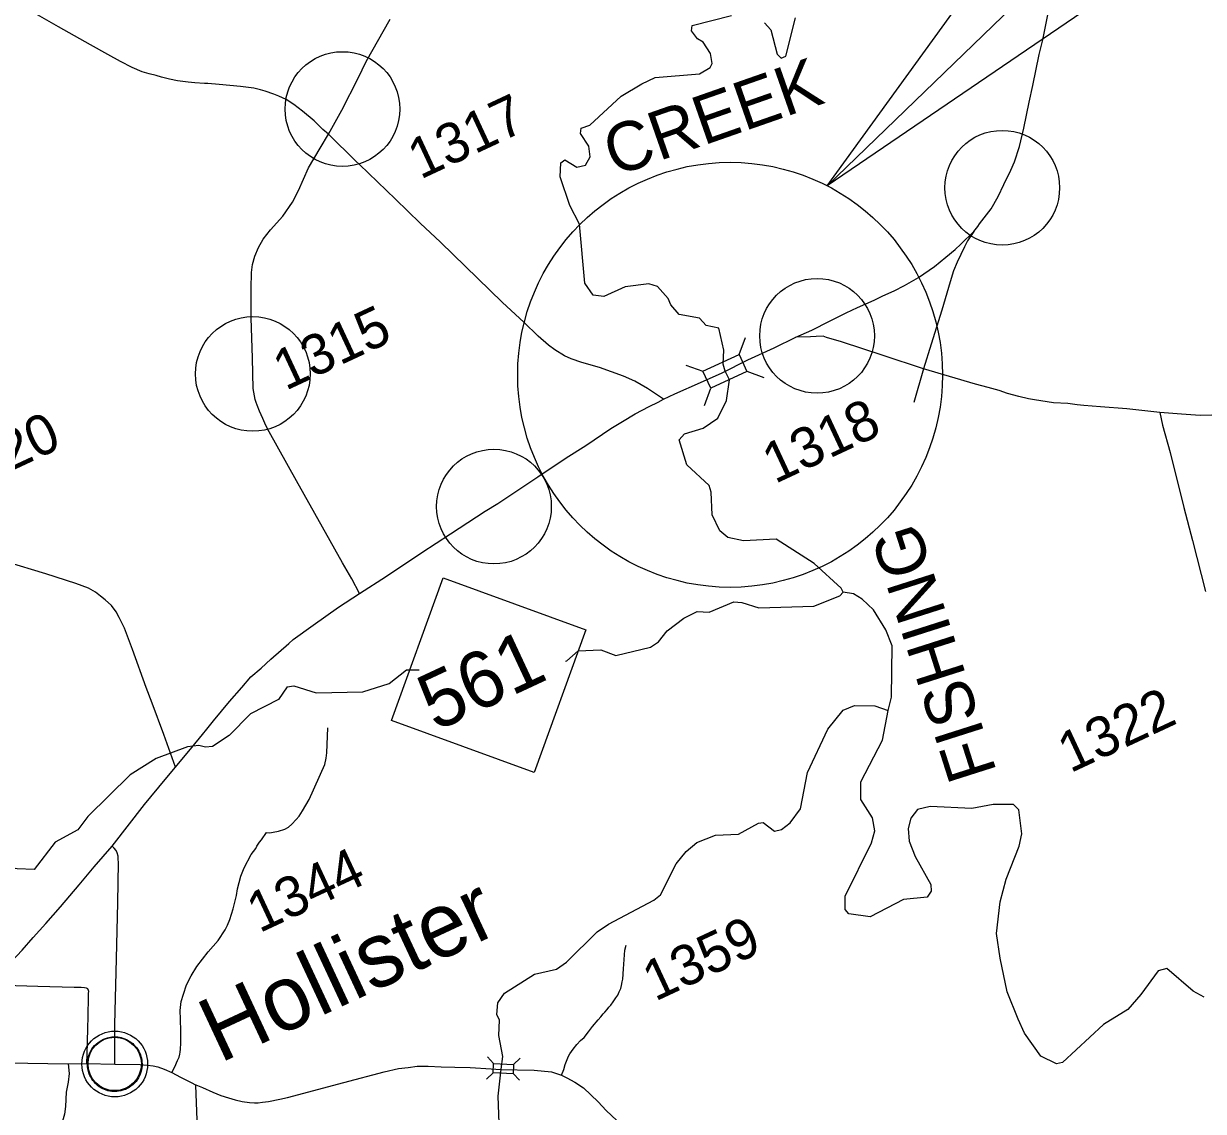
# Model space of a CAD drawing. Extents: x 2318983 to 2324558, y 920396 to 924651.
# Drawn here: x 2320442.5 to 2320802.7, y 922779.6 to 923111.6 of the extents above; entities that cross this region are included whole.
import ezdxf

# ---------------------------------------------------------------- set-up
doc = ezdxf.new("R2010")
doc.units = 0
for name, color, linetype in [('Default', 7, 'Continuous'), ('Exist Civil Demographics City Label', 7, 'Continuous'), ('Exist Civil Demographics Community CELL', 7, 'Continuous'), ('Exist Hydrographic Creek Single Shore', 7, 'Continuous'), ('Exist Road Primary NC Attributed', 7, 'Continuous'), ('Exist Road Primary NC Shield CELL', 7, 'Continuous'), ('Exist Road Primary NC Shield Number Label', 7, 'Continuous'), ('Exist Road Primary NC Structure Standard Bridge CELL', 7, 'Continuous'), ('Exist Road Secondary Structure Standard Bridge CELL', 7, 'Continuous'), ('Exist Road Secondary Type 41 Attributed', 7, 'Continuous'), ('Exist Road Secondary Type 51 Attributed', 7, 'Continuous'), ('Exist Road Secondary Type 51 Number Label', 7, 'Continuous'), ('Pattern 3', 7, 'Continuous'), ('Prop Terminator CELL', 7, 'Continuous')]:
    doc.layers.add(name, color=color, linetype=linetype)

msp = doc.modelspace()

# ---------------------------------------------------------------- linework, layer by layer
at = {"layer": 'Exist Civil Demographics Community CELL'}
msp.add_lwpolyline([(2320462.07, 922795.34), (2320462.18, 922795.94), (2320462.37, 922796.64), (2320462.68, 922797.4), (2320462.99, 922798.01), (2320463.34, 922798.62), (2320463.74, 922799.16), (2320464.16, 922799.63), (2320464.65, 922800.12), (2320465.24, 922800.61), (2320465.82, 922800.99), (2320466.33, 922801.3), (2320466.87, 922801.56), (2320467.45, 922801.8), (2320468.05, 922802), (2320468.51, 922802.12), (2320469.03, 922802.2), (2320469.46, 922802.28), (2320470.14, 922802.3), (2320470.61, 922802.29), (2320471.21, 922802.27), (2320471.74, 922802.19), (2320472.26, 922802.08), (2320472.79, 922801.93), (2320473.34, 922801.73), (2320474.05, 922801.42), (2320474.71, 922801.04), (2320475.25, 922800.67), (2320475.8, 922800.24), (2320476.15, 922799.91), (2320476.59, 922799.44), (2320477, 922798.94), (2320477.33, 922798.45), (2320477.66, 922797.92), (2320477.92, 922797.37), (2320478.14, 922796.84), (2320478.3, 922796.31), (2320478.44, 922795.82), (2320478.55, 922795.18), (2320478.62, 922794.68), (2320478.65, 922794.04), (2320478.63, 922793.42), (2320478.57, 922792.82), (2320478.47, 922792.24), (2320478.29, 922791.58), (2320478.09, 922790.96), (2320477.85, 922790.42), (2320477.51, 922789.79), (2320477.17, 922789.22), (2320476.8, 922788.72), (2320476.35, 922788.22), (2320475.79, 922787.69), (2320475.25, 922787.25), (2320474.72, 922786.89), (2320474.26, 922786.62), (2320473.54, 922786.28), (2320472.78, 922785.99), (2320472.15, 922785.83), (2320471.44, 922785.69), (2320470.97, 922785.64), (2320470.5, 922785.62), (2320469.9, 922785.62), (2320469.45, 922785.66), (2320468.85, 922785.74), (2320468.22, 922785.88), (2320467.73, 922786.02), (2320467.18, 922786.21), (2320466.69, 922786.43), (2320466.28, 922786.66), (2320465.55, 922787.1), (2320464.96, 922787.55), (2320464.44, 922788.03), (2320463.97, 922788.54), (2320463.63, 922788.97), (2320463.31, 922789.41), (2320462.88, 922790.16), (2320462.69, 922790.54), (2320462.51, 922790.97), (2320462.24, 922791.84), (2320462.07, 922792.59), (2320462, 922793.14), (2320461.96, 922793.81), (2320461.96, 922794.31), (2320462.02, 922794.99)], close=True, dxfattribs=at)
for centre, radius in [((2320470.32, 922794.02), 10.03), ((2320470.29, 922794.05), 8.15)]:
    msp.add_circle(centre, radius, dxfattribs=at)
at = {"layer": 'Exist Hydrographic Creek Single Shore'}
for points in [[(2320644.25, 922986.36), (2320649.98, 922988.04), (2320654.46, 922991.14), (2320657.07, 922996.49), (2320658, 923002.85), (2320656.69, 923005.48), (2320656.05, 923007.63), (2320656.28, 923011.88), (2320654.78, 923018.61), (2320650.87, 923019.41), (2320648.8, 923021.67), (2320642.63, 923022.79), (2320640.14, 923025.68), (2320639.31, 923027.66), (2320635.98, 923031.32), (2320633.33, 923032.1), (2320626.14, 923031.24), (2320619.62, 923028.31), (2320616.35, 923028.66), (2320613.84, 923032.35), (2320612.21, 923050.37), (2320609.29, 923056.07), (2320606.31, 923064.83), (2320606.48, 923069.11), (2320607.69, 923069.97), (2320611.4, 923067.78), (2320614.06, 923068.38), (2320615.49, 923070.86), (2320615.04, 923074.15), (2320612.53, 923078), (2320612.71, 923079.63), (2320615.36, 923080.54), (2320624.91, 923089.41), (2320631.23, 923093.15), (2320635.29, 923095.09), (2320648.83, 923096.21), (2320652.07, 923098.12), (2320652.69, 923099.36), (2320652.25, 923102.41), (2320649.93, 923105.87), (2320648.28, 923106.93), (2320646.41, 923109.36), (2320646.61, 923110.98), (2320658.66, 923113.98)], [(2320668.73, 923111.81), (2320670.6, 923109.62), (2320672.52, 923102.27), (2320673.77, 923101.03), (2320675.2, 923101.66), (2320678.15, 923113.32)], [(2320692.75, 922938.03), (2320692.11, 922939.3), (2320683.84, 922946.79), (2320672.28, 922954.23), (2320662.24, 922953.74), (2320657.51, 922954.68), (2320655.03, 922956.76), (2320652.72, 922961.59), (2320652.44, 922968.6), (2320651.8, 922970.59), (2320644.97, 922976.94), (2320642.63, 922984.51), (2320644.25, 922986.36)], [(2320607.89, 922916.97), (2320608.3, 922917.04), (2320611.78, 922920.17), (2320618.74, 922920.46), (2320623.26, 922918.71), (2320633.89, 922921.24), (2320636.33, 922922.88), (2320638.96, 922926.22), (2320644.03, 922930.14), (2320648.11, 922932.08), (2320651.8, 922931.91), (2320659.36, 922935.05), (2320661.82, 922934.91), (2320666.96, 922933.26), (2320683.77, 922933.71), (2320691.71, 922936.86), (2320692.75, 922938.03)], [(2320706.45, 922901.93), (2320707.43, 922906.01), (2320707.68, 922921.61), (2320705.76, 922926.54), (2320702.02, 922932.6), (2320698.5, 922935.85), (2320695.82, 922937.51), (2320692.75, 922938.03)], [(2320522.93, 922909.18), (2320524.97, 922909.42), (2320531.76, 922907.28), (2320546.1, 922907.63), (2320554.08, 922910.13), (2320559.37, 922914.3), (2320563.24, 922914.32)], [(2320522.93, 922909.18), (2320520.32, 922905.27), (2320511.76, 922900.88), (2320505.26, 922894.24), (2320500.17, 922890.96), (2320497.97, 922890.76), (2320495.95, 922891.18), (2320494.22, 922891.05), (2320492.48, 922890.83), (2320483, 922887.27), (2320475.05, 922882.26), (2320462.06, 922869.61), (2320459.03, 922865.45), (2320452.12, 922861.69), (2320445.65, 922853.43), (2320440.51, 922853.62), (2320434.16, 922854.57), (2320432.29, 922857)], [(2320587.98, 922767.86), (2320587.39, 922784.23), (2320588.32, 922792.4), (2320588.8, 922796.35), (2320587.61, 922802.73), (2320587.76, 922807.42), (2320586.92, 922809.08), (2320587.3, 922812.73), (2320589.31, 922815.64), (2320598.49, 922821.43), (2320605.23, 922823), (2320608.28, 922825.06), (2320617.61, 922834.41), (2320621.08, 922836.65), (2320634.93, 922844), (2320636.95, 922845.62), (2320641.77, 922855.1), (2320644.8, 922858.86), (2320648.06, 922861.58), (2320653.78, 922863.83), (2320660.74, 922864.12), (2320666.84, 922867.52), (2320668.26, 922867.74), (2320671.79, 922865.06), (2320673.85, 922865.55), (2320676.48, 922867.59), (2320679.71, 922871.93), (2320681.85, 922883), (2320688.07, 922896.17), (2320692.72, 922902.02), (2320696.19, 922903.45), (2320702.34, 922903.3), (2320706.45, 922901.93)], [(2320802.9, 922814.4), (2320799.61, 922816.28), (2320791.54, 922823.14), (2320788.88, 922822.46), (2320783.63, 922815.22), (2320779.58, 922810.69), (2320772.24, 922806.11), (2320759.65, 922794.53), (2320757.83, 922794.05), (2320753.08, 922796.44), (2320748.08, 922803.42), (2320746.19, 922807.71), (2320742.82, 922816.05), (2320740.68, 922826.3), (2320739.57, 922833.84), (2320740.68, 922843.5), (2320742.45, 922850.44), (2320746.46, 922860.53), (2320747.22, 922864.28), (2320746.34, 922871.59), (2320744.69, 922873.22), (2320738.54, 922873.21), (2320731.99, 922872.05), (2320719.27, 922872.58), (2320715.39, 922871.69), (2320713.37, 922869.03), (2320712.58, 922865.93), (2320712.82, 922862.06), (2320714.72, 922857.37), (2320719.52, 922848.77), (2320719.54, 922846.75), (2320718.34, 922844.92), (2320711.18, 922844.23), (2320700.97, 922838.96), (2320694.4, 922839.9), (2320693.36, 922841.15), (2320693.31, 922845.27), (2320701.34, 922861.51), (2320702.34, 922865.18), (2320701.68, 922869.11), (2320698.14, 922874.78), (2320698.06, 922880.11), (2320704.71, 922892.9), (2320706.45, 922901.93)]]:
    msp.add_lwpolyline(points, dxfattribs=at)
at = {"layer": 'Exist Road Primary NC Attributed'}
for points in [[(2320732.66, 923048.13), (2320733.83, 923049.63), (2320734.37, 923050.46), (2320735.81, 923052.27), (2320737.88, 923055.06), (2320739.99, 923058.75), (2320741.75, 923062.4), (2320743.95, 923066.81), (2320744.98, 923069.33), (2320746.6, 923074.01), (2320747.91, 923079.63), (2320749.48, 923087.6), (2320750.65, 923092.69), (2320752.58, 923102.16), (2320753.71, 923106.59), (2320755.77, 923117.28)], [(2320678.26, 923015.87), (2320683.12, 923018.03), (2320688.52, 923020.73), (2320693.64, 923023.24), (2320697.08, 923024.86), (2320702.14, 923027.18), (2320704.87, 923028.5), (2320708.31, 923030.02), (2320711.43, 923031.63), (2320715.75, 923034.02), (2320720.56, 923037.44), (2320724.07, 923040.32), (2320726.86, 923042.62), (2320728.66, 923044.19), (2320732.66, 923048.13)], [(2320655.75, 923005), (2320663.65, 923008.9), (2320671.61, 923012.63), (2320678.26, 923015.87)], [(2320717.29, 923006.2), (2320704.97, 923010.3), (2320692.2, 923014.4), (2320687.66, 923015.73), (2320686.63, 923016.19), (2320684.52, 923016.05), (2320682.75, 923015.94), (2320678.26, 923015.87)], [(2320637.83, 922996.9), (2320641.34, 922998.52), (2320649.12, 923002.01), (2320655.75, 923005)], [(2320789.45, 922992.87), (2320779.28, 922993.95), (2320771.3, 922994.63), (2320766.24, 922995.04), (2320764.17, 922995.24), (2320761.35, 922995.56), (2320756.92, 922995.84), (2320751.15, 922996.73), (2320749.34, 922997.05), (2320746.36, 922997.74), (2320742.89, 922998.71), (2320740.31, 922999.55), (2320736.97, 923000.48), (2320733.16, 923001.56), (2320717.29, 923006.2)], [(2320545.05, 922937.61), (2320553.29, 922942.92), (2320564.03, 922950.14), (2320572.8, 922955.81), (2320583.42, 922962.74), (2320587.28, 922965.13), (2320599.47, 922973.23), (2320608.15, 922979.01), (2320614.13, 922982.79), (2320621.76, 922988.01), (2320625.33, 922990.11), (2320629.2, 922992.49), (2320633.47, 922994.74), (2320636.18, 922996.06), (2320637.83, 922996.9)], [(2320831.33, 922998.26), (2320828.3, 922996.98), (2320824.41, 922995.55), (2320819.54, 922994.43), (2320815.04, 922993.68), (2320809.58, 922992.78), (2320805.23, 922992.03), (2320801.71, 922991.95), (2320796.02, 922992.33), (2320789.45, 922992.87)], [(2320488.84, 922884.62), (2320493.8, 922890.58), (2320497.08, 922894.61), (2320498.39, 922896.25), (2320500.44, 922898.76), (2320505.37, 922904.71), (2320509.06, 922908.97), (2320511.86, 922912.15), (2320514.96, 922914.82), (2320517.95, 922917.58), (2320523.43, 922922.34), (2320524.74, 922923.58), (2320530.9, 922927.98), (2320538.66, 922933.44), (2320545.05, 922937.61)], [(2320469.54, 922860.53), (2320479.39, 922873.19), (2320485.74, 922880.83), (2320488.84, 922884.62)], [(2320432.86, 922819.55), (2320434.02, 922820.69), (2320437.15, 922823.6), (2320442.08, 922828.76), (2320445.43, 922832.6), (2320449.23, 922836.86), (2320453.73, 922841.99), (2320459.42, 922848.69), (2320464.03, 922854.21), (2320469.54, 922860.53)]]:
    msp.add_lwpolyline(points, dxfattribs=at)
at = {"layer": 'Exist Road Primary NC Shield CELL'}
for p, q in [((2320554.8, 922898.86), (2320570.63, 922942.42)), ((2320570.63, 922942.42), (2320614.19, 922926.58)), ((2320614.19, 922926.58), (2320598.35, 922883.02)), ((2320598.35, 922883.02), (2320554.8, 922898.86))]:
    msp.add_line(p, q, dxfattribs=at)
at = {"layer": 'Exist Road Primary NC Structure Standard Bridge CELL'}
for p, q in [((2320660.95, 923010.52), (2320662.88, 923015.75)), ((2320644.64, 923007.35), (2320649.87, 923005.43)), ((2320663.29, 923005.47), (2320668.52, 923003.54)), ((2320650.34, 922995.03), (2320652.26, 923000.26))]:
    msp.add_line(p, q, dxfattribs=at)
msp.add_lwpolyline([(2320649.87, 923005.43), (2320660.94, 923010.55), (2320663.33, 923005.37), (2320652.26, 923000.26)], close=True, dxfattribs=at)
at = {"layer": 'Exist Road Secondary Structure Standard Bridge CELL'}
for p, q in [((2320584.09, 922796.21), (2320585.97, 922794.16)), ((2320592.07, 922793.89), (2320594.12, 922795.78)), ((2320583.8, 922789.43), (2320585.85, 922791.32)), ((2320591.95, 922791.11), (2320593.84, 922789.06))]:
    msp.add_line(p, q, dxfattribs=at)
msp.add_lwpolyline([(2320585.97, 922794.16), (2320592.07, 922793.91), (2320591.95, 922791.06), (2320585.85, 922791.32)], close=True, dxfattribs=at)
at = {"layer": 'Exist Road Secondary Type 41 Attributed'}
msp.add_lwpolyline([(2320732.66, 923048.13), (2320730.69, 923045.22), (2320729.75, 923043.4), (2320727.5, 923038.72), (2320726.42, 923036.15), (2320725.39, 923032.78), (2320722.87, 923024.14), (2320719.63, 923013.74), (2320717.29, 923006.2)], dxfattribs=at)
at = {"layer": 'Exist Road Secondary Type 51 Attributed'}
for p, q in [((2320717.29, 923006.2), (2320714.28, 922995.94)), ((2320456.12, 922794.03), (2320461.65, 922794.13)), ((2320461.65, 922794.13), (2320470.32, 922794.02))]:
    msp.add_line(p, q, dxfattribs=at)
for points in [[(2320535.56, 923077.85), (2320533.83, 923079.27), (2320531.21, 923081.88), (2320527.68, 923084.84), (2320525, 923086.87), (2320522.62, 923088.42), (2320520.45, 923089.38), (2320518.83, 923090.07), (2320516.25, 923090.91), (2320514.76, 923091.36), (2320512.75, 923091.84), (2320508.67, 923092.32), (2320502.19, 923092.97), (2320498.75, 923093.25), (2320497.7, 923093.24), (2320494.76, 923093.51), (2320492.72, 923093.72), (2320489.51, 923094.14), (2320487.05, 923094.59), (2320484.54, 923095.22), (2320482.98, 923095.67), (2320480.85, 923096.24), (2320478.66, 923096.87), (2320475.59, 923098.15), (2320472.03, 923100.03), (2320468.17, 923102.1), (2320462.88, 923105.09), (2320453.18, 923110.6), (2320446.05, 923114.6)], [(2320535.56, 923077.85), (2320533.83, 923079.27), (2320531.21, 923081.88), (2320527.68, 923084.84), (2320525, 923086.87), (2320522.62, 923088.42), (2320520.45, 923089.38), (2320518.83, 923090.07), (2320516.25, 923090.91), (2320514.76, 923091.36), (2320512.75, 923091.84), (2320508.67, 923092.32), (2320502.19, 923092.97), (2320498.75, 923093.25), (2320497.7, 923093.24), (2320494.76, 923093.51), (2320492.72, 923093.72), (2320489.51, 923094.14), (2320487.05, 923094.59), (2320484.54, 923095.22), (2320482.98, 923095.67), (2320480.85, 923096.24), (2320478.66, 923096.87), (2320475.59, 923098.15), (2320472.03, 923100.03), (2320468.17, 923102.1), (2320462.88, 923105.09), (2320453.18, 923110.6), (2320446.05, 923114.6)], [(2320535.56, 923077.85), (2320539.64, 923085.12), (2320544.6, 923094.89), (2320547.12, 923100.03), (2320554.4, 923112.93)], [(2320545.05, 922937.61), (2320542.67, 922942.12), (2320539.81, 922947), (2320533.71, 922957.9), (2320525.82, 922972.03), (2320517.46, 922986.92), (2320516.45, 922988.85), (2320515.57, 922990.99), (2320514.52, 922993.3), (2320513.77, 922995.1), (2320513.53, 922995.91), (2320513.2, 922996.84), (2320512.57, 923000.18), (2320512.36, 923009.45), (2320511.97, 923021.76), (2320511.94, 923030.76), (2320512.03, 923035.56), (2320512.39, 923037.99), (2320513.08, 923040.54), (2320514.19, 923043.21), (2320515.63, 923045.73), (2320517.85, 923048.58), (2320521.59, 923052.78), (2320524.53, 923057.04), (2320526.42, 923060.64), (2320529.51, 923067.51), (2320533.05, 923073.59), (2320535.56, 923077.85)], [(2320637.83, 922996.9), (2320633.02, 923000.14), (2320629.11, 923002.46), (2320625.6, 923003.99), (2320618.3, 923006.57), (2320612.87, 923008.13), (2320609.66, 923009.23), (2320607.63, 923010.19), (2320604.64, 923011.95), (2320602.77, 923013.41), (2320599.56, 923016.12), (2320595.23, 923020.41), (2320588.66, 923026.47), (2320569.77, 923044.87), (2320563.57, 923050.68), (2320556.04, 923057.97), (2320545, 923068.57), (2320543.96, 923069.57), (2320535.56, 923077.85)], [(2320789.45, 922992.87), (2320790.25, 922989.03), (2320792.59, 922980.63), (2320796.74, 922963.82), (2320799.33, 922953.77), (2320803.38, 922938.26)], [(2320488.84, 922884.62), (2320485.26, 922894.56), (2320481.7, 922904.15), (2320479.94, 922908.91), (2320475.69, 922920.53), (2320473.25, 922927.04), (2320471.69, 922930.32), (2320470.74, 922931.98), (2320469.29, 922933.94), (2320467.36, 922935.73), (2320465.97, 922936.85), (2320464.43, 922938.01), (2320462.3, 922939.22), (2320458.45, 922940.66), (2320449.22, 922943.66), (2320437.13, 922947.31)], [(2320516.65, 922864.66), (2320517.67, 922864.61), (2320518.72, 922864.73), (2320520.3, 922865.13), (2320522.26, 922865.72), (2320523.36, 922866.35), (2320524.41, 922867.22), (2320525.72, 922868.6), (2320526.57, 922869.71), (2320527.68, 922871.28), (2320529.71, 922874.76), (2320534.4, 922885.4), (2320534.84, 922887.36), (2320535.06, 922889.02), (2320535.39, 922896.58)], [(2320487.7, 922791.43), (2320488.61, 922793.17), (2320489.43, 922795.05), (2320489.96, 922796.08), (2320490.17, 922797.03), (2320490.26, 922797.67), (2320490.43, 922798.55), (2320490.5, 922800.43), (2320490.44, 922804), (2320490.35, 922807.66), (2320490.29, 922810.39), (2320490.55, 922813.07), (2320491.25, 922815.36), (2320492.21, 922818.18), (2320493.63, 922820.97), (2320495.37, 922823.73), (2320498.86, 922828.29), (2320501.93, 922831.73), (2320504, 922835), (2320504.78, 922836.43), (2320505.45, 922838.11), (2320506.49, 922841.41), (2320507.45, 922845.42), (2320507.83, 922847.44), (2320508.82, 922851.3), (2320509.86, 922853.93), (2320511.92, 922858), (2320513.38, 922859.79), (2320513.66, 922860.51), (2320514.48, 922861.76), (2320515.1, 922862.48), (2320516.65, 922864.66)], [(2320470.32, 922794.02), (2320470.38, 922806.06), (2320470.85, 922826.08), (2320471.25, 922843.3), (2320471.43, 922855.45), (2320471.39, 922856.64), (2320471.3, 922857.5), (2320471.06, 922858.47), (2320470.77, 922859.2), (2320470.17, 922859.9), (2320469.54, 922860.53)], [(2320606.71, 922790.64), (2320607.39, 922792.38), (2320607.88, 922793.83), (2320608.85, 922796.43), (2320609.29, 922797.1), (2320610.29, 922798.51), (2320611.38, 922799.96), (2320612.54, 922801.19), (2320613.61, 922802.09), (2320614.97, 922803.82), (2320616.22, 922805.44), (2320617.87, 922807.5), (2320618.73, 922808.44), (2320619.41, 922809.29), (2320619.97, 922809.88), (2320620.69, 922810.61), (2320621.21, 922811.33), (2320621.74, 922811.98), (2320622.5, 922813.02), (2320623.31, 922814.19), (2320623.87, 922815), (2320624.36, 922816.05), (2320624.8, 922817.06), (2320625.04, 922817.98), (2320625.28, 922819.07), (2320625.41, 922819.96), (2320625.69, 922823.11), (2320626.09, 922828.75), (2320626.49, 922830.32)], [(2320432.86, 922819.55), (2320433.93, 922818.84), (2320434.59, 922818.64), (2320435.52, 922818.4), (2320437.13, 922818.15), (2320440.08, 922817.96), (2320446.86, 922817.73), (2320457.92, 922817.49), (2320460.05, 922817.45), (2320461.02, 922817.38), (2320461.58, 922817.24), (2320461.94, 922817.05), (2320462.22, 922816.59), (2320462.25, 922816.22), (2320462.23, 922815.59), (2320462.21, 922814.67), (2320462.07, 922808.51), (2320462, 922804.85), (2320461.79, 922796.89), (2320461.65, 922794.13)], [(2320403.89, 922794.66), (2320405.66, 922794.59), (2320406.82, 922794.6), (2320425.14, 922794.59), (2320456.12, 922794.03)], [(2320456.12, 922794.03), (2320456.36, 922791.13), (2320456.12, 922788.51), (2320455.49, 922785.39), (2320455.28, 922781.06), (2320454.97, 922778.68), (2320454.55, 922777.29), (2320454.06, 922775.37), (2320453.4, 922772.96), (2320452.56, 922769.99), (2320451.48, 922766.32), (2320450.5, 922762.69), (2320449.39, 922758.33), (2320448.11, 922753.14), (2320442.71, 922752.73)], [(2320470.32, 922794.02), (2320478.03, 922793.84), (2320479.11, 922793.8), (2320480.3, 922793.62), (2320482.02, 922793.44), (2320483.5, 922793.16), (2320485.43, 922792.49), (2320487.7, 922791.43)], [(2320487.7, 922791.43), (2320490.37, 922789.99), (2320493.63, 922788.4), (2320494.97, 922787.68)], [(2320494.97, 922787.68), (2320495.11, 922787.62), (2320497.1, 922786.81), (2320500.21, 922785.47), (2320502.73, 922784.42), (2320505, 922783.65), (2320507.12, 922783.04), (2320509.24, 922782.57), (2320511.49, 922782.23), (2320513.02, 922782.15), (2320514.08, 922782.22), (2320515.46, 922782.38), (2320517.26, 922782.55), (2320520.7, 922783.33), (2320523.1, 922783.8), (2320540.21, 922788.38), (2320552.59, 922791.64), (2320556.94, 922792.61), (2320559.89, 922792.97), (2320562.67, 922793.38), (2320565.97, 922793.38), (2320569.93, 922793.16), (2320574.16, 922793.01), (2320578.82, 922792.95), (2320585.24, 922792.54)], [(2320585.24, 922792.54), (2320588.04, 922792.36), (2320598.37, 922792.19), (2320603.65, 922791.61), (2320605.18, 922791.17), (2320606.71, 922790.64)], [(2320606.71, 922790.64), (2320608.32, 922789.8), (2320610.8, 922788.47), (2320613.42, 922786.73), (2320617.89, 922782.46), (2320620.39, 922779.88), (2320623.65, 922776.77), (2320624.82, 922775.89), (2320625.95, 922775.2), (2320627.88, 922774.15), (2320630.06, 922773.1), (2320632.8, 922772.14), (2320638.08, 922770.6), (2320648.35, 922767.6), (2320649.52, 922767.2)], [(2320494.97, 922787.68), (2320494.98, 922787.49), (2320495.9, 922763.88), (2320496.28, 922753.33), (2320496.74, 922746.52), (2320496.86, 922744.52), (2320497.03, 922742.29), (2320497.27, 922739.14), (2320497.55, 922736.47), (2320497.86, 922732.63), (2320498.1, 922729.68), (2320498.23, 922727.01), (2320498.37, 922724.61), (2320498.58, 922721.49), (2320498.88, 922717.9), (2320499.23, 922712.89), (2320499.68, 922704.04)]]:
    msp.add_lwpolyline(points, dxfattribs=at)
at = {"layer": 'Pattern 3'}
msp.add_line((2320812.16, 923182.33), (2320687.87, 923062.03), dxfattribs=at)
for centre, radius in [((2320539.83, 923085.48), 17.51), ((2320741.29, 923061.45), 17.51), ((2320658.19, 923004.36), 64.86), ((2320684.75, 923016.26), 17.51), ((2320512.47, 923004.64), 17.51), ((2320586.09, 922964.16), 17.51)]:
    msp.add_circle(centre, radius, dxfattribs=at)
at = {"layer": 'Prop Terminator CELL'}
msp.add_lwpolyline([(2320797.42, 923136.74), (2320687.87, 923062.03), (2320766.13, 923170.11), (2320770.29, 923141.81)], close=True, dxfattribs=at)

# ---------------------------------------------------------------- texts
at = {"layer": 'Default'}
for s, rotation, p in [('CREEK', 19.2762, (2320622.89, 923064.81)), ('FISHING', 107.6915, (2320739.71, 922883.13))]:
    msp.add_text(s, height=14.881, rotation=rotation, dxfattribs=at).set_placement(p)
at = {"layer": 'Exist Civil Demographics City Label'}
msp.add_text('Hollister', height=19.683, rotation=25.0187, dxfattribs=at).set_placement((2320502.36, 922794.15))
at = {"layer": 'Exist Road Primary NC Shield Number Label'}
msp.add_text('561', height=17.223, rotation=25.0187, dxfattribs=at).set_placement((2320568.26, 922895.4))
at = {"layer": 'Exist Road Secondary Type 51 Number Label'}
for s, p in [('1317', (2320563.62, 923063.89)), ('1315', (2320522.46, 922999.43)), ('1318', (2320671.87, 922970.99)), ('1320', (2320421.48, 922966.91)), ('1322', (2320762.06, 922882.71)), ('1344', (2320514.46, 922833.89)), ('1359', (2320635.29, 922813))]:
    msp.add_text(s, height=12.302, rotation=25.0187, dxfattribs=at).set_placement(p)

doc.saveas('drawing.dxf')
